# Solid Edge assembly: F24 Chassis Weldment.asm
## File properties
Author: chasteen
Template: Ansi Inch Weldment.asm
Last saved by: z0cbxm
Revision: 197
Application: Solid Edge
Weld Bead Density: 0.000 lbm/in^3
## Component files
F24 Chassis Inch.asm
SquareTubing 1.25x1.25x.06.par
RoundTubing1.25x.065.par
Seatbelt Mount.par
SquareTubing 1x1x.06.par
motor mount connecter.par
Seat.asm
RoundTubing 1x.065.par
Front Plate.psm
battery clamp connecter.par
Motor Mount Stud.asm
wheel connector.par
Steering Mount.par
Steering Mount 2.par
Angle-.75x.75x.125.par
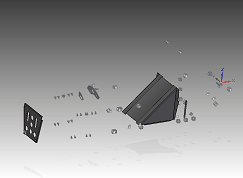
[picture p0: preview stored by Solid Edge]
